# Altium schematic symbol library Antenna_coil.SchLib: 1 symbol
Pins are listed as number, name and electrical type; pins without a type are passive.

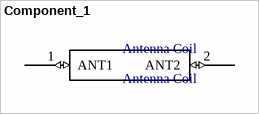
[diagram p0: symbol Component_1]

## Component_1
designator Antenna Coil, comment Antenna Coil
footprint PCBComponent_1
pins: 1 ANT1 (io), 2 ANT2 (io)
